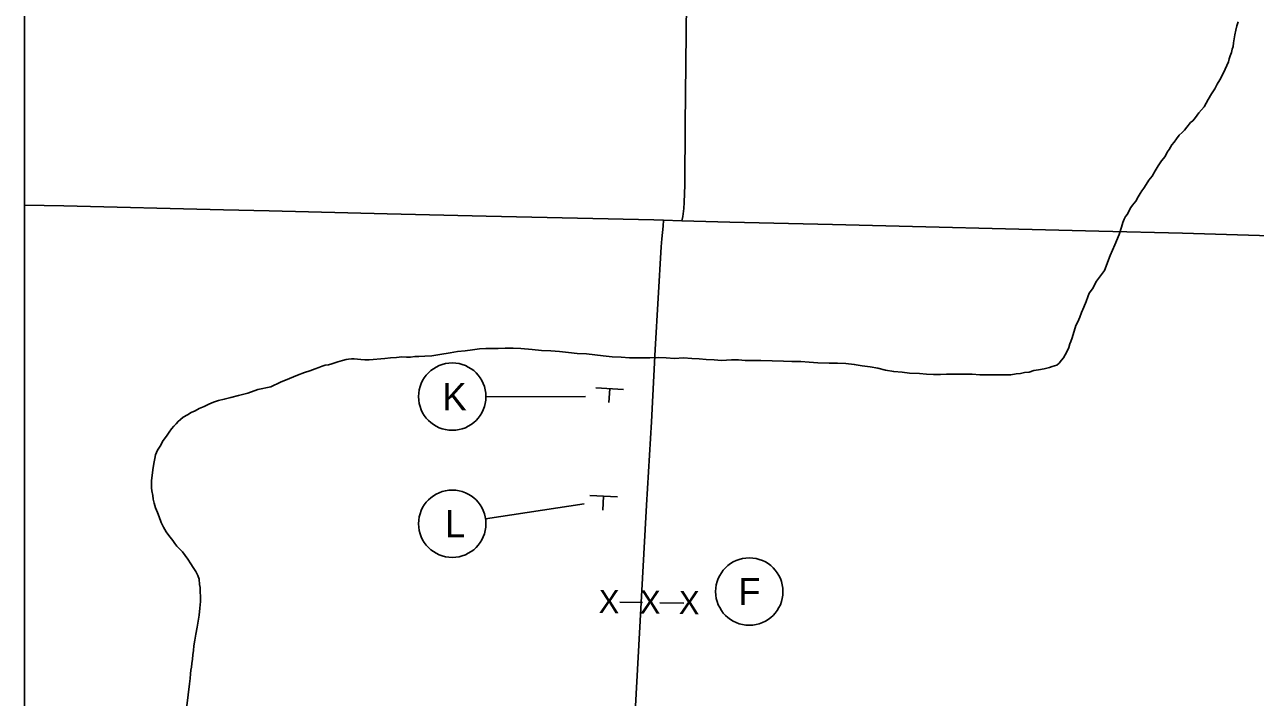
# Model space of a CAD drawing. Extents: x 1633.3 to 1707.6, y 1081.5 to 1106.
# Drawn here: x 1633.31 to 1640.38, y 1090.29 to 1094.16 of the extents above; entities that cross this region are included whole.
import ezdxf

# ---------------------------------------------------------------- set-up
doc = ezdxf.new("R2010")
doc.units = 0
for name, color, linetype in [('GM_X_County_Road', 7, 'Continuous'), ('GM_X_Minor_River', 7, 'Continuous'), ('GM_X_Township_Road', 7, 'Continuous'), ('SH_Data', 7, 'Continuous'), ('SH_Text', 7, 'Continuous'), ('SN_P_Signs', 7, 'Continuous')]:
    doc.layers.add(name, color=color, linetype=linetype)

msp = doc.modelspace()

# ---------------------------------------------------------------- linework, layer by layer
at = {"layer": 'GM_X_County_Road'}
for points in [[(1637.0896, 1093.0279), (1637.0949, 1093.0534), (1637.0993, 1093.083), (1637.1007, 1093.0976), (1637.1027, 1093.1331), (1637.1057, 1093.2355), (1637.1076, 1093.5806), (1637.115, 1094.2812)], [(1636.7895, 1089.5915), (1636.8181, 1090.1691), (1636.886, 1091.3924), (1636.9148, 1091.8728), (1636.9362, 1092.288), (1636.9703, 1092.8778), (1636.974, 1092.925), (1636.9808, 1092.9969), (1636.984, 1093.031)], [(1636.984, 1093.031), (1637.0896, 1093.0279)]]:
    msp.add_lwpolyline(points, dxfattribs=at)
at = {"layer": 'GM_X_Minor_River'}
for points in [[(1640.2784, 1094.1479), (1640.273, 1094.1238), (1640.2676, 1094.0971), (1640.2622, 1094.073), (1640.2595, 1094.0516), (1640.2567, 1094.0302), (1640.2513, 1094.0142), (1640.2486, 1093.9955), (1640.2406, 1093.9768), (1640.2352, 1093.9581), (1640.2298, 1093.942), (1640.2217, 1093.9207), (1640.2109, 1093.8993), (1640.1975, 1093.8699), (1640.1814, 1093.8379), (1640.1653, 1093.8138), (1640.1518, 1093.7871), (1640.133, 1093.7577), (1640.1142, 1093.7257), (1640.09, 1093.683), (1640.0605, 1093.6483), (1640.0417, 1093.6216), (1640.0256, 1093.6029), (1640.0122, 1093.5923), (1639.9908, 1093.5656), (1639.9774, 1093.5496), (1639.9639, 1093.5362), (1639.9478, 1093.5202), (1639.9317, 1093.4989), (1639.9183, 1093.4802), (1639.9049, 1093.4642), (1639.8968, 1093.4508), (1639.8888, 1093.4375), (1639.878, 1093.4215), (1639.8673, 1093.3974), (1639.8458, 1093.3734), (1639.827, 1093.344), (1639.8082, 1093.3147), (1639.7921, 1093.2853), (1639.7733, 1093.2613), (1639.7572, 1093.2372), (1639.7438, 1093.2159), (1639.733, 1093.1999), (1639.7223, 1093.1838), (1639.7116, 1093.1651), (1639.6981, 1093.1411), (1639.6793, 1093.1171), (1639.6686, 1093.1037), (1639.6605, 1093.0877), (1639.6498, 1093.0663), (1639.6391, 1093.053), (1639.631, 1093.037), (1639.6229, 1093.0183), (1639.6148, 1092.9915), (1639.6014, 1092.9488), (1639.5771, 1092.89), (1639.5502, 1092.8285), (1639.5179, 1092.743), (1639.4723, 1092.6816), (1639.4481, 1092.6362), (1639.4293, 1092.6122), (1639.4213, 1092.5908), (1639.4132, 1092.5641), (1639.3997, 1092.532), (1639.3863, 1092.5), (1639.3755, 1092.4733), (1639.3647, 1092.4465), (1639.354, 1092.4252), (1639.3324, 1092.3557), (1639.3244, 1092.3343), (1639.319, 1092.3209), (1639.3136, 1092.2995), (1639.3028, 1092.2782), (1639.2921, 1092.2568), (1639.2813, 1092.2408), (1639.2706, 1092.2274), (1639.2572, 1092.2088), (1639.2438, 1092.1981), (1639.217, 1092.1902), (1639.2009, 1092.1849), (1639.1715, 1092.1769), (1639.1394, 1092.1717), (1639.1126, 1092.1664), (1639.0858, 1092.1585), (1639.059, 1092.1559), (1639.035, 1092.1506), (1639.0109, 1092.148), (1638.9787, 1092.1428), (1638.9439, 1092.1429), (1638.8878, 1092.1431), (1638.845, 1092.1432), (1638.8021, 1092.1433), (1638.7566, 1092.1461), (1638.7192, 1092.1463), (1638.6817, 1092.1464), (1638.6469, 1092.1465), (1638.6095, 1092.1466), (1638.5747, 1092.1441), (1638.5346, 1092.1442), (1638.4944, 1092.147), (1638.4543, 1092.1498)], [(1640.2865, 1094.172), (1640.2784, 1094.1479)], [(1638.4543, 1092.1498), (1638.3981, 1092.1526), (1638.3553, 1092.1581), (1638.3072, 1092.1609), (1638.259, 1092.1691), (1638.2162, 1092.18), (1638.1708, 1092.1881), (1638.1253, 1092.1936), (1638.0798, 1092.2018), (1638.0317, 1092.2073), (1637.9835, 1092.2101), (1637.9353, 1092.2103), (1637.8711, 1092.2105), (1637.8203, 1092.216), (1637.7721, 1092.2189), (1637.7213, 1092.219), (1637.6731, 1092.2218), (1637.542, 1092.2249), (1637.4992, 1092.2251), (1637.4537, 1092.2252), (1637.4136, 1092.228), (1637.3735, 1092.2281), (1637.3173, 1092.2257), (1637.2745, 1092.2285), (1637.229, 1092.2313), (1637.1889, 1092.2341), (1637.1461, 1092.2369), (1637.0979, 1092.2397), (1637.047, 1092.2372), (1636.9989, 1092.24), (1636.9534, 1092.2429), (1636.9052, 1092.2403), (1636.8544, 1092.2405), (1636.7875, 1092.2407), (1636.7394, 1092.2435), (1636.6885, 1092.2464), (1636.6377, 1092.2519), (1636.5895, 1092.2574), (1636.5414, 1092.2629), (1636.4879, 1092.2657), (1636.4371, 1092.2713), (1636.3862, 1092.2768), (1636.3354, 1092.2796), (1636.2819, 1092.2825), (1636.2284, 1092.288), (1636.1642, 1092.2935), (1636.1187, 1092.2963), (1636.0732, 1092.2965), (1636.0331, 1092.2939), (1635.9983, 1092.2941), (1635.9635, 1092.2942), (1635.926, 1092.2916), (1635.8859, 1092.2864), (1635.843, 1092.2812), (1635.8002, 1092.276), (1635.7574, 1092.2681), (1635.6985, 1092.2602), (1635.653, 1092.2523), (1635.6129, 1092.2498), (1635.5781, 1092.2472), (1635.554, 1092.2473), (1635.5299, 1092.2447), (1635.5058, 1092.2448), (1635.4791, 1092.2449), (1635.4496, 1092.2423), (1635.4148, 1092.2397), (1635.3827, 1092.2372), (1635.2917, 1092.2294), (1635.2676, 1092.2295), (1635.2436, 1092.2296), (1635.2248, 1092.2323), (1635.2061, 1092.2351), (1635.1901, 1092.2351), (1635.174, 1092.2325), (1635.1606, 1092.2298), (1635.1392, 1092.2246), (1635.1124, 1092.2166), (1635.0776, 1092.206), (1635.0589, 1092.2007), (1635.0401, 1092.1981), (1635.0214, 1092.1928), (1635.0027, 1092.1849), (1634.9812, 1092.1769), (1634.9518, 1092.1663), (1634.9196, 1092.1557), (1634.8795, 1092.1398), (1634.8339, 1092.1212), (1634.783, 1092.0999), (1634.7268, 1092.0734), (1634.6518, 1092.0575), (1634.5956, 1092.0363), (1634.542, 1092.0231), (1634.4965, 1092.0126), (1634.459, 1092.002), (1634.4269, 1091.9941), (1634.3975, 1091.9861), (1634.3707, 1091.9728), (1634.3439, 1091.9595), (1634.3144, 1091.9489), (1634.293, 1091.9356), (1634.2689, 1091.925)], [(1634.2689, 1091.925), (1634.2475, 1091.9117), (1634.2233, 1091.8984), (1634.2073, 1091.8851), (1634.1939, 1091.8744), (1634.1831, 1091.8611), (1634.1697, 1091.8477), (1634.1563, 1091.8317), (1634.1429, 1091.813), (1634.1268, 1091.789), (1634.108, 1091.765), (1634.0919, 1091.7329), (1634.0758, 1091.7089), (1634.065, 1091.6822), (1634.0596, 1091.6608), (1634.0569, 1091.6421), (1634.0514, 1091.61), (1634.0406, 1091.5351), (1634.0405, 1091.5137), (1634.0405, 1091.4923), (1634.0431, 1091.4762), (1634.0484, 1091.4495), (1634.051, 1091.4281), (1634.0563, 1091.404), (1634.0643, 1091.3772), (1634.0749, 1091.3504), (1634.0856, 1091.3263), (1634.0962, 1091.2941), (1634.1095, 1091.2673), (1634.1255, 1091.2405), (1634.1415, 1091.2191), (1634.1629, 1091.1896), (1634.1762, 1091.1735), (1634.1869, 1091.1574), (1634.2029, 1091.1413), (1634.2189, 1091.1252), (1634.2349, 1091.1037), (1634.2509, 1091.0823), (1634.2669, 1091.0555), (1634.2802, 1091.034), (1634.2962, 1091.0126), (1634.3069, 1090.9885), (1634.3149, 1090.967), (1634.3175, 1090.9376), (1634.3201, 1090.9189), (1634.32, 1090.8921), (1634.3227, 1090.8707), (1634.3226, 1090.8386), (1634.3198, 1090.8011), (1634.3144, 1090.761), (1634.309, 1090.7263), (1634.3035, 1090.6915), (1634.2954, 1090.6514), (1634.29, 1090.6166), (1634.2846, 1090.5845), (1634.2818, 1090.5578), (1634.2791, 1090.5337), (1634.2764, 1090.507), (1634.2736, 1090.4829), (1634.2709, 1090.4615), (1634.2682, 1090.4455), (1634.2655, 1090.4241), (1634.2627, 1090.3973), (1634.26, 1090.3652), (1634.2436, 1090.2395)]]:
    msp.add_lwpolyline(points, dxfattribs=at)
at = {"layer": 'GM_X_Township_Road'}
for points in [[(1633.3121, 1093.1177), (1633.5373, 1093.1131), (1634.4558, 1093.0918), (1634.7182, 1093.0847), (1635.3962, 1093.0687), (1635.9648, 1093.0549), (1636.4897, 1093.0425), (1636.9271, 1093.0328), (1636.984, 1093.031)], [(1637.0896, 1093.0279), (1637.3644, 1093.0196), (1637.9549, 1093.0061), (1639.4858, 1092.9677), (1639.9669, 1092.956), (1640.5354, 1092.9402), (1640.6274, 1092.9386)]]:
    msp.add_lwpolyline(points, dxfattribs=at)
at = {"layer": 'SH_Data'}
msp.add_lwpolyline([(1633.3121, 1106.0207), (1648.0121, 1106.0207), (1648.0121, 1086.4207), (1633.3121, 1086.4207)], close=True, dxfattribs=at)
at = {"layer": 'SH_Text'}
for p, q in [((1636.5361, 1092.017), (1635.9632, 1092.0153)), ((1636.5275, 1091.401), (1635.9613, 1091.3139))]:
    msp.add_line(p, q, dxfattribs=at)
for centre in [(1635.7696, 1092.017), (1635.7696, 1091.2866), (1637.4766, 1090.8964)]:
    msp.add_circle(centre, 0.1936, dxfattribs=at)
at = {"layer": 'SN_P_Signs'}
for p, q in [((1636.7541, 1092.0585), (1636.5943, 1092.0667)), ((1636.6742, 1092.0626), (1636.6701, 1091.9827)), ((1636.7193, 1091.4405), (1636.5595, 1091.4487)), ((1636.6394, 1091.4446), (1636.6353, 1091.3647)), ((1636.7331, 1090.835), (1636.8632, 1090.8333)), ((1636.9634, 1090.832), (1637.1002, 1090.8302))]:
    msp.add_line(p, q, dxfattribs=at)

# ---------------------------------------------------------------- texts
at = {"layer": 'SH_Text'}
for s, p in [('K', (1635.7131, 1091.939)), ('L', (1635.7272, 1091.2086)), ('F', (1637.4133, 1090.8184))]:
    msp.add_text(s, height=0.156, dxfattribs=at).set_placement(p)
at = {"layer": 'SN_P_Signs'}
for p in [(1636.6102, 1090.7731), (1636.8472, 1090.77), (1637.0708, 1090.7671)]:
    msp.add_text('X', height=0.1333, rotation=359.25135, dxfattribs=at).set_placement(p)

doc.saveas('drawing.dxf')
